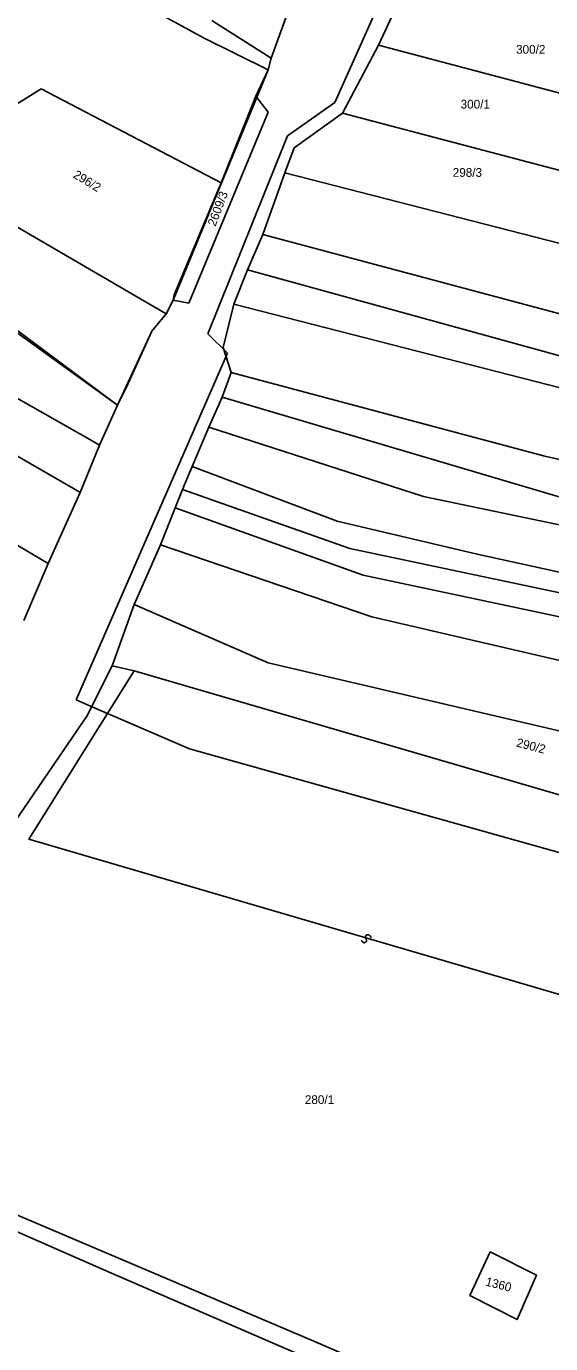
# Model space of a CAD drawing. Extents: x -581999 to -572728, y -1219553 to -1212032.
# Drawn here: x -576815.8 to -576696.1, y -1214969 to -1214668.1 of the extents above; entities that cross this region are included whole.
import ezdxf

# ---------------------------------------------------------------- set-up
doc = ezdxf.new("R2010")
doc.units = 0
for name, color, linetype in [('Vrstva 1', 7, 'Continuous'), ('Vrstva 2', 7, 'Continuous'), ('Vrstva 4', 7, 'Continuous'), ('Vrstva 6', 7, 'Continuous'), ('Vrstva 61', 7, 'Continuous')]:
    doc.layers.add(name, color=color, linetype=linetype)

msp = doc.modelspace()

# ---------------------------------------------------------------- linework, layer by layer
at = {"layer": 'Vrstva 1'}
for p, q in [((-576833.313, -1214695.385), (-576812.386, -1214682.41)), ((-576812.386, -1214682.41), (-576771.308, -1214703.886)), ((-576763.438, -1214684.073), (-576760.601, -1214687.733)), ((-576760.601, -1214687.733), (-576778.69, -1214731.316)), ((-576783.884, -1214733.753), (-576838.988, -1214701.706)), ((-576778.69, -1214731.316), (-576782.237, -1214730.651))]:
    msp.add_line(p, q, dxfattribs=at)
for points in [[(-576752.189, -1214654.004), (-576756.7, -1214666.546), (-576759.891, -1214675.423), (-576760.601, -1214678.085), (-576763.438, -1214684.073), (-576771.308, -1214703.886), (-576782.05, -1214729.442), (-576782.237, -1214730.651), (-576783.884, -1214733.753), (-576787.143, -1214737.716)], [(-576735.374, -1214672.395), (-576728.632, -1214657.823)], [(-576917.751, -1214662.217), (-576858.851, -1214706.697), (-576856.723, -1214708.693), (-576795.006, -1214754.605)], [(-576787.336, -1214664.153), (-576782.858, -1214666.644), (-576775.193, -1214670.803)], [(-576773.474, -1214666.814), (-576759.891, -1214675.423)], [(-576775.193, -1214670.803), (-576760.601, -1214678.085)], [(-576743.595, -1214687.953), (-576735.374, -1214672.395)], [(-576640.234, -1214697.628), (-576735.374, -1214672.395)], [(-576754.673, -1214695.844), (-576743.595, -1214687.953)], [(-576743.595, -1214687.953), (-576628.143, -1214718.43)], [(-576756.809, -1214701.57), (-576754.673, -1214695.844)], [(-576761.805, -1214715.668), (-576756.809, -1214701.57)], [(-576756.809, -1214701.57), (-576616.586, -1214737.55)], [(-576765.273, -1214723.761), (-576761.805, -1214715.668)], [(-576609.38, -1214756.383), (-576761.805, -1214715.668)], [(-576875.811, -1214720.217), (-576800.801, -1214762.77)], [(-576768.441, -1214731.555), (-576765.273, -1214723.761)], [(-576765.273, -1214723.761), (-576693.472, -1214743.494), (-576623.872, -1214760.329), (-576606.895, -1214766.068)], [(-576805.06, -1214773.663), (-576878.311, -1214731.422), (-576886.095, -1214726.98)], [(-576769.02, -1214747.188), (-576770.825, -1214741.479), (-576768.441, -1214731.555)], [(-576768.441, -1214731.555), (-576672.229, -1214756.252), (-576657.552, -1214759.806)], [(-576902.61, -1214738.662), (-576840.595, -1214773.219), (-576810.8, -1214790.769)], [(-576787.143, -1214737.716), (-576793.036, -1214750.675)], [(-576771.123, -1214752.791), (-576769.02, -1214747.188)], [(-576599.075, -1214792.325), (-576637.625, -1214780.085), (-576697.752, -1214766.231), (-576769.02, -1214747.188)], [(-576793.036, -1214750.675), (-576795.006, -1214754.605), (-576799.097, -1214763.807)], [(-576774.136, -1214759.683), (-576771.123, -1214752.791)], [(-576596.599, -1214801.429), (-576639.246, -1214788.191), (-576691.364, -1214776.425), (-576771.123, -1214752.791)], [(-576777.906, -1214768.674), (-576774.136, -1214759.683)], [(-576774.136, -1214759.683), (-576725.124, -1214775.51), (-576673.664, -1214786.255), (-576640.738, -1214793.584), (-576594.274, -1214809.667)], [(-576800.801, -1214762.77), (-576799.097, -1214763.807)], [(-576799.097, -1214763.807), (-576803.517, -1214774.582)], [(-576780.165, -1214773.917), (-576777.906, -1214768.674)], [(-576712.895, -1214788.642), (-576744.801, -1214781.094), (-576777.906, -1214768.674)], [(-576803.517, -1214774.582), (-576810.8, -1214790.769)], [(-576805.06, -1214773.663), (-576803.517, -1214774.582)], [(-576781.826, -1214778.113), (-576780.165, -1214773.917)], [(-576780.165, -1214773.917), (-576741.933, -1214787.394), (-576646.062, -1214807.631), (-576588.529, -1214828.099)], [(-576785.147, -1214786.504), (-576781.826, -1214778.113)], [(-576586.782, -1214833.872), (-576649.969, -1214812.304), (-576738.912, -1214793.49), (-576781.826, -1214778.113)], [(-576791.171, -1214800.135), (-576785.147, -1214786.504)], [(-576785.147, -1214786.504), (-576736.933, -1214803.004), (-576645.549, -1214824.213)], [(-576590.184, -1214821.732), (-576641.696, -1214804.259), (-576712.895, -1214788.642)], [(-576816.358, -1214803.806), (-576810.8, -1214790.769)], [(-576796.201, -1214814.154), (-576791.171, -1214800.135)], [(-576595.25, -1214858.644), (-576661.663, -1214836.592), (-576760.556, -1214813.49), (-576791.171, -1214800.135)], [(-576850.27, -1214885.089), (-576845.076, -1214888.688), (-576801.951, -1214825.671), (-576796.201, -1214814.154)], [(-576796.201, -1214814.154), (-576791.18, -1214815.295)], [(-576791.18, -1214815.295), (-576692.529, -1214844.083)], [(-576666.812, -1215009.494), (-576721.865, -1214985.095), (-576796.846, -1214952.656), (-576875.331, -1214918.224)], [(-576866.054, -1214918.201), (-576823.412, -1214937.275), (-576749.605, -1214968.632), (-576674.033, -1215001.536)], [(-576714.521, -1214957.959), (-576703.755, -1214963.459), (-576699.339, -1214953.288), (-576709.908, -1214948.013), (-576714.521, -1214957.959)]]:
    msp.add_lwpolyline(points, dxfattribs=at)
at = {"layer": 'Vrstva 4'}
msp.add_lwpolyline([(-576672.216, -1214895.577), (-576815.212, -1214853.714), (-576791.18, -1214815.295)], dxfattribs=at)
at = {"layer": 'Vrstva 6'}
msp.add_open_spline([(-576739.349, -1214876.824), (-576738.869, -1214877.531), (-576738.175, -1214877.22), (-576738.098, -1214876.82), (-576738.334, -1214876.475), (-576738.419, -1214876.143), (-576738.337, -1214875.853), (-576738.193, -1214875.673), (-576737.957, -1214875.545), (-576737.592, -1214875.581), (-576737.165, -1214876.02), (-576737.11, -1214876.193)], degree=2, dxfattribs=at)
at = {"layer": 'Vrstva 61'}
for p, q in [((-576955.878, -1214638.589), (-576795.006, -1214754.605)), ((-576745.39, -1214685.5), (-576724.97, -1214639.77)), ((-576759.891, -1214675.423), (-576752.189, -1214654.004)), ((-576760.601, -1214678.085), (-576759.891, -1214675.423)), ((-576782.237, -1214730.651), (-576760.601, -1214678.085)), ((-576756.14, -1214693.13), (-576745.39, -1214685.5)), ((-576774.37, -1214738.35), (-576756.14, -1214693.13)), ((-576783.884, -1214733.753), (-576782.237, -1214730.651)), ((-576787.143, -1214737.716), (-576783.884, -1214733.753)), ((-576795.006, -1214754.605), (-576787.143, -1214737.716)), ((-576769.88, -1214742.79), (-576774.37, -1214738.35)), ((-576804.42, -1214821.92), (-576769.88, -1214742.79)), ((-576801.66, -1214823.11), (-576804.42, -1214821.92)), ((-576778.52, -1214833.1), (-576801.66, -1214823.11)), ((-576687.09, -1214858.76), (-576778.52, -1214833.1))]:
    msp.add_line(p, q, dxfattribs=at)

# ---------------------------------------------------------------- texts
at = {"layer": 'Vrstva 2'}
for s, p in [('300/2', (-576704.001, -1214674.375)), ('300/1', (-576716.663, -1214686.9)), ('298/3', (-576718.456, -1214702.49)), ('280/1', (-576752.221, -1214914.234))]:
    msp.add_text(s, height=2, dxfattribs=at).set_placement(p)
for s, rotation, p in [('296/2', 328.60804, (-576805.277, -1214702.529)), ('2609/3', 69.25021, (-576772.615, -1214713.928)), ('290/2', 345.49486, (-576704.061, -1214832.564)), ('1360', 345.49486, (-576711.115, -1214955.644))]:
    msp.add_text(s, height=2, rotation=rotation, dxfattribs=at).set_placement(p)

doc.saveas('drawing.dxf')
